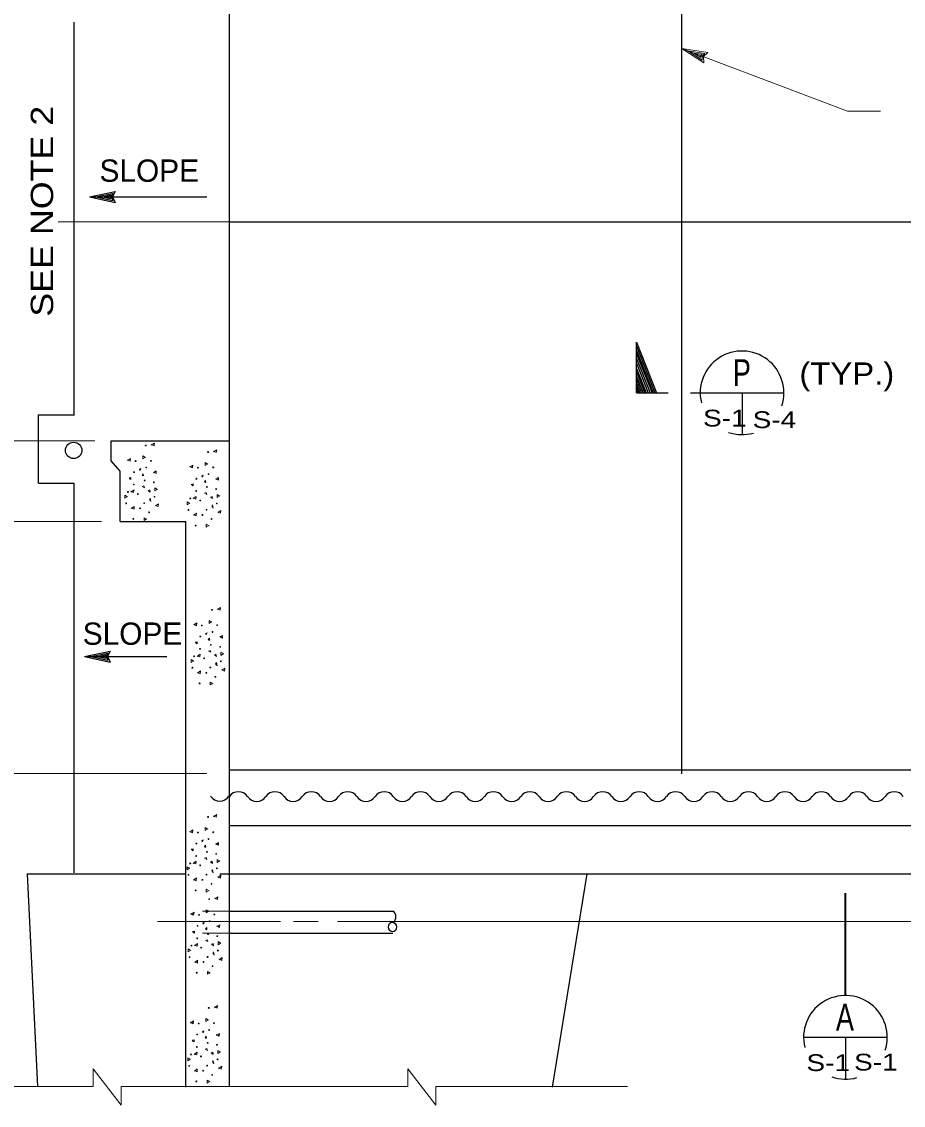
# Model space of a CAD drawing. Extents: x -24.3 to 17.7, y -17.6 to 12.4.
# Drawn here: x -19.54 to -14.6, y -0.2 to 5.87 of the extents above; entities that cross this region are included whole.
import ezdxf
from ezdxf.enums import TextEntityAlignment as Align

# ---------------------------------------------------------------- set-up
doc = ezdxf.new("R2010")
doc.units = 0
doc.header["$LTSCALE"] = 0.05
doc.linetypes.add('MEDIUM_DASHED', pattern=[4.5, 3, -1.5])
doc.layers.add('1', color=7, linetype='Continuous', lineweight=13)
doc.layers.add('2', color=7, linetype='Continuous', lineweight=13)

msp = doc.modelspace()

# ---------------------------------------------------------------- linework, layer by layer
at = {"layer": '1', "lineweight": 25}
for p, q in [((-18.37569, -0.0986), (-18.37569, 9.5474)), ((-15.84269, 1.6534), (-15.84269, 7.8164)), ((-19.24569, 3.6614), (-19.24569, 5.8654)), ((-19.15969, 4.8854), (-19.01569, 4.9164)), ((-19.15969, 4.8854), (-18.50169, 4.8854)), ((-19.15969, 4.8854), (-19.01569, 4.8544)), ((-19.12269, 4.8854), (-19.02869, 4.9054)), ((-19.12269, 4.8854), (-19.02869, 4.8654)), ((-19.08669, 4.8854), (-19.04169, 4.8954)), ((-19.08669, 4.8854), (-19.04169, 4.8764)), ((-19.04169, 4.8954), (-19.04569, 4.8854)), ((-19.04569, 4.8854), (-19.04169, 4.8764)), ((-19.02869, 4.9054), (-19.03769, 4.8854)), ((-19.03769, 4.8854), (-19.02869, 4.8654)), ((-18.37569, 4.7464), (-10.12369, 4.7464)), ((-19.44469, 3.2814), (-19.44469, 3.6644)), ((-19.44469, 3.6644), (-19.24569, 3.6644)), ((-19.03769, 3.4064), (-19.03769, 3.5184)), ((-19.03769, 3.5184), (-18.37969, 3.5184)), ((-18.98669, 3.3494), (-19.03769, 3.4064)), ((-18.98669, 3.0674), (-18.98669, 3.3494)), ((-19.44469, 3.2814), (-19.24569, 3.2814)), ((-19.24569, 1.0994), (-19.24569, 3.2814)), ((-18.98669, 3.0674), (-18.61869, 3.0674)), ((-18.61869, -0.1016), (-18.61869, 3.0674)), ((-19.18769, 2.3104), (-19.04369, 2.3414)), ((-19.18769, 2.3104), (-18.72669, 2.3104)), ((-19.18769, 2.3104), (-19.04369, 2.2794)), ((-19.15069, 2.3104), (-19.05669, 2.3304)), ((-19.15069, 2.3104), (-19.05669, 2.2904)), ((-19.11469, 2.3104), (-19.06969, 2.3204)), ((-19.11469, 2.3104), (-19.06969, 2.3014)), ((-19.06969, 2.3204), (-19.07369, 2.3104)), ((-19.07369, 2.3104), (-19.06969, 2.3014)), ((-19.05669, 2.3304), (-19.06569, 2.3104)), ((-19.06569, 2.3104), (-19.05669, 2.2904)), ((-18.37569, 1.6764), (-10.43869, 1.6764)), ((-18.37569, 1.3644), (-10.47069, 1.3644)), ((-19.50869, 1.0934), (-18.61869, 1.0934)), ((-19.50869, 1.0934), (-19.45069, -0.0986)), ((-18.42869, 1.0934), (-10.49869, 1.0934)), ((-16.37469, 1.0934), (-16.56869, -0.1026)), ((-18.37569, 0.8844), (-17.45969, 0.8844)), ((-18.37569, 0.7614), (-17.46069, 0.7614))]:
    msp.add_line(p, q, dxfattribs=at)
at = {"layer": '1'}
for p, q in [((-14.91369, 5.3654), (-15.84269, 5.7174)), ((-15.84269, 5.7174), (-15.69669, 5.6954)), ((-15.84269, 5.7174), (-15.71869, 5.6374)), ((-15.80769, 5.7044), (-15.71269, 5.6894)), ((-15.80769, 5.7044), (-15.72769, 5.6524)), ((-15.77469, 5.6914), (-15.73569, 5.6674)), ((-15.77469, 5.6914), (-15.72869, 5.6854)), ((-15.72869, 5.6854), (-15.73569, 5.6774)), ((-15.73569, 5.6774), (-15.73569, 5.6674)), ((-15.71269, 5.6894), (-15.72869, 5.6744)), ((-15.72869, 5.6744), (-15.72769, 5.6524)), ((-14.91369, 5.3654), (-14.72969, 5.3654)), ((-18.37569, 4.7464), (-19.33469, 4.7464)), ((-19.12869, 3.5184), (-20.37669, 3.5184)), ((-19.09169, 3.0674), (-20.33369, 3.0674)), ((-18.50269, 1.6554), (-21.16869, 1.6554)), ((-18.77869, 0.8254), (-18.08969, 0.8254)), ((-18.01569, 0.8254), (-17.87869, 0.8254)), ((-17.76969, 0.8254), (-13.92869, 0.8254)), ((-19.13869, -0.0986), (-19.13869, 0.0014)), ((-18.98069, -0.2036), (-19.13869, 0.0014)), ((-17.37669, -0.0986), (-17.37669, 0.0014)), ((-17.21869, -0.2036), (-17.37669, 0.0014)), ((-19.69369, -0.0986), (-19.13869, -0.0986)), ((-18.98069, -0.2036), (-18.98069, -0.0986)), ((-18.98069, -0.0986), (-17.37669, -0.0986)), ((-17.21869, -0.2036), (-17.21869, -0.0986)), ((-17.21869, -0.0986), (-16.14669, -0.0986))]:
    msp.add_line(p, q, dxfattribs=at)
at = {"layer": '1', "lineweight": 35}
msp.add_line((-14.92469, 0.4114), (-14.92469, 0.9844), dxfattribs=at)
at = {"layer": '1', "linetype": 'MEDIUM_DASHED'}
for p, q in [((-18.37569, 0.8844), (-18.61869, 0.8844)), ((-18.37569, 0.7614), (-18.61869, 0.7614))]:
    msp.add_line(p, q, dxfattribs=at)
at = {"layer": '1'}
msp.add_lwpolyline([(-15.69669, 5.6954), (-15.72069, 5.6714), (-15.71869, 5.6374)], dxfattribs=at)
at = {"layer": '1', "lineweight": 25}
for points in [[(-19.01569, 4.9164), (-19.02969, 4.8854), (-19.01569, 4.8544)], [(-19.04369, 2.3414), (-19.05769, 2.3104), (-19.04369, 2.2794)]]:
    msp.add_lwpolyline(points, dxfattribs=at)
msp.add_circle((-19.24769, 3.4654), 0.04597, dxfattribs=at)
for centre, radius, start, end in [((-18.42969, 1.5629), 0.06157, 214.0772, 325.92281), ((-18.32469, 1.4919), 0.06157, 34.0772, 145.92281), ((-18.22269, 1.5609), 0.06157, 214.0772, 325.92281), ((-18.12069, 1.4919), 0.06157, 34.0772, 145.92281), ((-18.01869, 1.5609), 0.06157, 214.0772, 325.92281), ((-17.91669, 1.4919), 0.06157, 34.0772, 145.92281), ((-17.81469, 1.5609), 0.06157, 214.0772, 325.92281), ((-17.71269, 1.4919), 0.06157, 34.0772, 145.92281), ((-17.61069, 1.5609), 0.06157, 214.0772, 325.92281), ((-17.50869, 1.4919), 0.06157, 34.0772, 145.92281), ((-17.40669, 1.5609), 0.06157, 214.0772, 325.92281), ((-17.30469, 1.4919), 0.06157, 34.0772, 145.92281), ((-17.20269, 1.5609), 0.06157, 214.0772, 325.92281), ((-17.10069, 1.4919), 0.06157, 34.0772, 145.92281), ((-16.99869, 1.5609), 0.06157, 214.0772, 325.92281), ((-16.89669, 1.4919), 0.06157, 34.0772, 145.92281), ((-16.79469, 1.5609), 0.06157, 214.0772, 325.92281), ((-16.69269, 1.4919), 0.06157, 34.0772, 145.92281), ((-16.59069, 1.5609), 0.06157, 214.0772, 325.92281), ((-16.48869, 1.4919), 0.06157, 34.0772, 145.92281), ((-16.38669, 1.5609), 0.06157, 214.0772, 325.92281), ((-16.28469, 1.4919), 0.06157, 34.0772, 145.92281), ((-16.18269, 1.5609), 0.06157, 214.0772, 325.92281), ((-16.08069, 1.4919), 0.06157, 34.0772, 145.92281), ((-15.97869, 1.5609), 0.06157, 214.0772, 325.92281), ((-15.87669, 1.4919), 0.06157, 34.0772, 145.92281), ((-15.77469, 1.5609), 0.06157, 214.0772, 325.92281), ((-15.67269, 1.4919), 0.06157, 34.0772, 145.92281), ((-15.57069, 1.5609), 0.06157, 214.0772, 325.92281), ((-15.46869, 1.4919), 0.06157, 34.0772, 145.92281), ((-15.36669, 1.5609), 0.06157, 214.0772, 325.92281), ((-15.26469, 1.4919), 0.06157, 34.0772, 145.92281), ((-15.16269, 1.5609), 0.06157, 214.0772, 325.92281), ((-15.06069, 1.4919), 0.06157, 34.0772, 145.92281), ((-14.95869, 1.5609), 0.06157, 214.0772, 325.92281), ((-14.85669, 1.4919), 0.06157, 34.0772, 145.92281), ((-14.75469, 1.5609), 0.06157, 214.0772, 325.92281), ((-14.65269, 1.4919), 0.06157, 34.0772, 145.92281), ((-17.48075, 0.85268), 0.03807, 307.28682, 56.4084)]:
    msp.add_arc(centre, radius, start, end, dxfattribs=at)
msp.add_ellipse((-17.46219, 0.7954), major_axis=(-0.0005, 0.027), ratio=0.833928, dxfattribs=at)
at = {"layer": '2', "lineweight": 25}
for p, q in [((-16.09569, 4.0494), (-15.99269, 3.7884)), ((-16.09569, 4.0244), (-16.00169, 3.7884)), ((-16.09569, 4.0074), (-16.00869, 3.7884)), ((-16.09569, 3.9804), (-16.01969, 3.7884)), ((-16.09569, 3.9544), (-16.02969, 3.7884)), ((-16.09569, 3.9244), (-16.04169, 3.7884)), ((-16.09569, 3.9034), (-16.04969, 3.7884)), ((-16.09569, 3.8794), (-16.05869, 3.7884)), ((-16.09569, 3.8584), (-16.06769, 3.7884)), ((-16.09569, 3.8364), (-16.07669, 3.7884)), ((-16.09569, 3.8214), (-16.08269, 3.7884)), ((-16.09569, 3.8014), (-16.09069, 3.7884)), ((-16.09569, 3.7884), (-15.91869, 3.7884)), ((-15.79369, 3.7884), (-15.73869, 3.7884)), ((-15.73869, 3.7884), (-15.27069, 3.7884)), ((-15.50469, 3.7884), (-15.50469, 3.5544)), ((-15.15969, 0.1774), (-14.69169, 0.1774)), ((-14.92569, 0.1774), (-14.92569, -0.0566))]:
    msp.add_line(p, q, dxfattribs=at)
at = {"layer": '2'}
for p, q in [((-18.92869, 3.3034), (-18.93669, 3.3124)), ((-18.57969, 3.2664), (-18.58769, 3.2754)), ((-18.55769, 2.3824), (-18.56569, 2.3914)), ((-18.57969, 1.2224), (-18.58769, 1.2314)), ((-18.57369, 0.7614), (-18.58169, 0.7704)), ((-18.57569, 0.1524), (-18.58369, 0.1614))]:
    msp.add_line(p, q, dxfattribs=at)
at = {"layer": '2', "lineweight": 25}
msp.add_lwpolyline([(-16.09569, 3.7884), (-16.09569, 4.0724), (-15.98369, 3.7884)], dxfattribs=at)
at = {"layer": '2'}
for points in [[(-18.81269, 3.4984), (-18.79769, 3.4914), (-18.79569, 3.5064), (-18.81269, 3.4944)], [(-18.46369, 3.4614), (-18.44869, 3.4544), (-18.44669, 3.4694), (-18.46369, 3.4574)], [(-18.94569, 3.4124), (-18.93069, 3.4044), (-18.92869, 3.4204), (-18.94569, 3.4084)], [(-18.84769, 3.4254), (-18.86069, 3.4174), (-18.86069, 3.4344), (-18.84469, 3.4254)], [(-18.87669, 3.3534), (-18.87969, 3.3604), (-18.87169, 3.3644), (-18.87569, 3.3534)], [(-18.80069, 3.3434), (-18.78569, 3.3354), (-18.78469, 3.3504), (-18.80069, 3.3394)], [(-18.59669, 3.3754), (-18.58169, 3.3674), (-18.57969, 3.3834), (-18.59669, 3.3714)], [(-18.49869, 3.3884), (-18.51169, 3.3804), (-18.51169, 3.3974), (-18.49569, 3.3884)], [(-18.93769, 3.3124), (-18.92669, 3.3144), (-18.92669, 3.3034)], [(-18.85769, 3.3224), (-18.86469, 3.3274), (-18.85769, 3.3344), (-18.85669, 3.3234)], [(-18.52769, 3.3164), (-18.53069, 3.3234), (-18.52269, 3.3274), (-18.52669, 3.3164)], [(-18.50869, 3.2854), (-18.51569, 3.2904), (-18.50869, 3.2974), (-18.50769, 3.2864)], [(-18.45169, 3.3064), (-18.43669, 3.2984), (-18.43569, 3.3134), (-18.45169, 3.3024)], [(-18.92669, 3.2364), (-18.91169, 3.2294), (-18.90969, 3.2444), (-18.92669, 3.2324)], [(-18.78069, 3.2464), (-18.79369, 3.2384), (-18.79369, 3.2554), (-18.77769, 3.2464)], [(-18.58869, 3.2754), (-18.57769, 3.2774), (-18.57769, 3.2664)], [(-18.43169, 3.2094), (-18.44469, 3.2014), (-18.44469, 3.2184), (-18.42869, 3.2094)], [(-18.94769, 3.2054), (-18.96069, 3.1974), (-18.96069, 3.2144), (-18.94569, 3.2054)], [(-18.81869, 3.1834), (-18.82369, 3.1904), (-18.81869, 3.1974), (-18.81569, 3.1794)], [(-18.78869, 3.1574), (-18.77369, 3.1504), (-18.77169, 3.1664), (-18.78869, 3.1544)], [(-18.59869, 3.1684), (-18.61169, 3.1604), (-18.61169, 3.1774), (-18.59669, 3.1684)], [(-18.57769, 3.1994), (-18.56269, 3.1924), (-18.56069, 3.2074), (-18.57769, 3.1954)], [(-18.46969, 3.1464), (-18.47469, 3.1534), (-18.46969, 3.1604), (-18.46669, 3.1424)], [(-18.92469, 3.1424), (-18.90969, 3.1354), (-18.90869, 3.1514), (-18.92469, 3.1394)], [(-18.57569, 3.1054), (-18.56069, 3.0984), (-18.55969, 3.1144), (-18.57569, 3.1024)], [(-18.43969, 3.1204), (-18.42469, 3.1134), (-18.42269, 3.1294), (-18.43969, 3.1174)], [(-18.84069, 3.0794), (-18.85369, 3.0724), (-18.85369, 3.0884), (-18.83869, 3.0794)], [(-18.49169, 3.0424), (-18.50469, 3.0354), (-18.50469, 3.0514), (-18.48969, 3.0424)], [(-18.44169, 2.5774), (-18.42669, 2.5704), (-18.42469, 2.5854), (-18.44169, 2.5734)], [(-18.57469, 2.4914), (-18.55969, 2.4834), (-18.55769, 2.4994), (-18.57469, 2.4874)], [(-18.47669, 2.5044), (-18.48969, 2.4964), (-18.48969, 2.5134), (-18.47369, 2.5044)], [(-18.50569, 2.4324), (-18.50869, 2.4394), (-18.50069, 2.4434), (-18.50469, 2.4324)], [(-18.42969, 2.4224), (-18.41469, 2.4144), (-18.41369, 2.4294), (-18.42969, 2.4184)], [(-18.56669, 2.3914), (-18.55569, 2.3934), (-18.55569, 2.3824)], [(-18.48669, 2.4014), (-18.49369, 2.4064), (-18.48669, 2.4134), (-18.48569, 2.4024)], [(-18.55569, 2.3154), (-18.54069, 2.3084), (-18.53869, 2.3234), (-18.55569, 2.3114)], [(-18.40969, 2.3254), (-18.42269, 2.3174), (-18.42269, 2.3344), (-18.40669, 2.3254)], [(-18.57669, 2.2844), (-18.58969, 2.2764), (-18.58969, 2.2934), (-18.57469, 2.2844)], [(-18.44769, 2.2624), (-18.45269, 2.2694), (-18.44769, 2.2764), (-18.44469, 2.2584)], [(-18.55369, 2.2214), (-18.53869, 2.2144), (-18.53769, 2.2304), (-18.55369, 2.2184)], [(-18.41769, 2.2364), (-18.40269, 2.2294), (-18.40069, 2.2454), (-18.41769, 2.2334)], [(-18.46969, 2.1584), (-18.48269, 2.1514), (-18.48269, 2.1674), (-18.46769, 2.1584)], [(-18.46369, 1.4174), (-18.44869, 1.4104), (-18.44669, 1.4254), (-18.46369, 1.4134)], [(-18.59669, 1.3314), (-18.58169, 1.3234), (-18.57969, 1.3394), (-18.59669, 1.3274)], [(-18.49869, 1.3444), (-18.51169, 1.3364), (-18.51169, 1.3534), (-18.49569, 1.3444)], [(-18.52769, 1.2724), (-18.53069, 1.2794), (-18.52269, 1.2834), (-18.52669, 1.2724)], [(-18.58869, 1.2314), (-18.57769, 1.2334), (-18.57769, 1.2224)], [(-18.50869, 1.2414), (-18.51569, 1.2464), (-18.50869, 1.2534), (-18.50769, 1.2424)], [(-18.45169, 1.2624), (-18.43669, 1.2544), (-18.43569, 1.2694), (-18.45169, 1.2584)], [(-18.57769, 1.1554), (-18.56269, 1.1484), (-18.56069, 1.1634), (-18.57769, 1.1514)], [(-18.43169, 1.1654), (-18.44469, 1.1574), (-18.44469, 1.1744), (-18.42869, 1.1654)], [(-18.59869, 1.1244), (-18.61169, 1.1164), (-18.61169, 1.1334), (-18.59669, 1.1244)], [(-18.46969, 1.1024), (-18.47469, 1.1094), (-18.46969, 1.1164), (-18.46669, 1.0984)], [(-18.57569, 1.0614), (-18.56069, 1.0544), (-18.55969, 1.0704), (-18.57569, 1.0584)], [(-18.43969, 1.0764), (-18.42469, 1.0694), (-18.42269, 1.0854), (-18.43969, 1.0734)], [(-18.49169, 0.9984), (-18.50469, 0.9914), (-18.50469, 1.0074), (-18.48969, 0.9984)], [(-18.45769, 0.9564), (-18.44269, 0.9494), (-18.44069, 0.9644), (-18.45769, 0.9524)], [(-18.59069, 0.8704), (-18.57569, 0.8624), (-18.57369, 0.8784), (-18.59069, 0.8664)], [(-18.49269, 0.8834), (-18.50569, 0.8754), (-18.50569, 0.8924), (-18.48969, 0.8834)], [(-18.52169, 0.8114), (-18.52469, 0.8184), (-18.51669, 0.8224), (-18.52069, 0.8114)], [(-18.50269, 0.7804), (-18.50969, 0.7854), (-18.50269, 0.7924), (-18.50169, 0.7814)], [(-18.44569, 0.8014), (-18.43069, 0.7934), (-18.42969, 0.8084), (-18.44569, 0.7974)], [(-18.58269, 0.7704), (-18.57169, 0.7724), (-18.57169, 0.7614)], [(-18.59269, 0.6634), (-18.60569, 0.6554), (-18.60569, 0.6724), (-18.59069, 0.6634)], [(-18.57169, 0.6944), (-18.55669, 0.6874), (-18.55469, 0.7024), (-18.57169, 0.6904)], [(-18.42569, 0.7044), (-18.43869, 0.6964), (-18.43869, 0.7134), (-18.42269, 0.7044)], [(-18.56969, 0.6004), (-18.55469, 0.5934), (-18.55369, 0.6094), (-18.56969, 0.5974)], [(-18.46369, 0.6414), (-18.46869, 0.6484), (-18.46369, 0.6554), (-18.46069, 0.6374)], [(-18.43369, 0.6154), (-18.41869, 0.6084), (-18.41669, 0.6244), (-18.43369, 0.6124)], [(-18.48569, 0.5374), (-18.49869, 0.5304), (-18.49869, 0.5464), (-18.48369, 0.5374)], [(-18.45969, 0.3474), (-18.44469, 0.3404), (-18.44269, 0.3554), (-18.45969, 0.3434)], [(-18.59269, 0.2614), (-18.57769, 0.2534), (-18.57569, 0.2694), (-18.59269, 0.2574)], [(-18.49469, 0.2744), (-18.50769, 0.2664), (-18.50769, 0.2834), (-18.49169, 0.2744)], [(-18.52369, 0.2024), (-18.52669, 0.2094), (-18.51869, 0.2134), (-18.52269, 0.2024)], [(-18.50469, 0.1714), (-18.51169, 0.1764), (-18.50469, 0.1834), (-18.50369, 0.1724)], [(-18.44769, 0.1924), (-18.43269, 0.1844), (-18.43169, 0.1994), (-18.44769, 0.1884)], [(-18.58469, 0.1614), (-18.57369, 0.1634), (-18.57369, 0.1524)], [(-18.59469, 0.0544), (-18.60769, 0.0464), (-18.60769, 0.0634), (-18.59269, 0.0544)], [(-18.57369, 0.0854), (-18.55869, 0.0784), (-18.55669, 0.0934), (-18.57369, 0.0814)], [(-18.42769, 0.0954), (-18.44069, 0.0874), (-18.44069, 0.1044), (-18.42469, 0.0954)], [(-18.57169, -0.0086), (-18.55669, -0.0156), (-18.55569, 0.0004), (-18.57169, -0.0116)], [(-18.46569, 0.0324), (-18.47069, 0.0394), (-18.46569, 0.0464), (-18.46269, 0.0284)], [(-18.43569, 0.0064), (-18.42069, -0.0006), (-18.41869, 0.0154), (-18.43569, 0.0034)], [(-18.48769, -0.0716), (-18.50069, -0.0786), (-18.50069, -0.0626), (-18.48569, -0.0716)]]:
    msp.add_lwpolyline(points, dxfattribs=at)
for points in [[(-18.85069, 3.2554), (-18.86369, 3.2624), (-18.85469, 3.2664)], [(-18.81869, 3.2324), (-18.83069, 3.2404), (-18.82169, 3.2444)], [(-18.50169, 3.2184), (-18.51469, 3.2254), (-18.50569, 3.2294)], [(-18.46969, 3.1954), (-18.48169, 3.2034), (-18.47269, 3.2074)], [(-18.47969, 2.3344), (-18.49269, 2.3414), (-18.48369, 2.3454)], [(-18.44769, 2.3114), (-18.45969, 2.3194), (-18.45069, 2.3234)], [(-18.50169, 1.1744), (-18.51469, 1.1814), (-18.50569, 1.1854)], [(-18.46969, 1.1514), (-18.48169, 1.1594), (-18.47269, 1.1634)], [(-18.49569, 0.7134), (-18.50869, 0.7204), (-18.49969, 0.7244)], [(-18.46369, 0.6904), (-18.47569, 0.6984), (-18.46669, 0.7024)], [(-18.49769, 0.1044), (-18.51069, 0.1114), (-18.50169, 0.1154)], [(-18.46569, 0.0814), (-18.47769, 0.0894), (-18.46869, 0.0934)]]:
    msp.add_lwpolyline(points, close=True, dxfattribs=at)
for centre in [(-18.84412, 3.49315), (-18.90075, 3.40577), (-18.81488, 3.40727), (-18.49512, 3.45615), (-18.90938, 3.3439), (-18.8415, 3.3694), (-18.55175, 3.36877), (-18.46588, 3.37027), (-18.85012, 3.2974), (-18.79838, 3.28615), (-18.56038, 3.3069), (-18.4925, 3.3324), (-18.9435, 3.2329), (-18.91088, 3.27452), (-18.888, 3.22165), (-18.56188, 3.23752), (-18.50112, 3.2604), (-18.44937, 3.24915), (-18.95362, 3.16877), (-18.85275, 3.1699), (-18.79462, 3.20515), (-18.5945, 3.1959), (-18.539, 3.18465), (-18.44562, 3.16815), (-18.87562, 3.14102), (-18.825, 3.11815), (-18.60462, 3.13177), (-18.52662, 3.10402), (-18.50375, 3.1329), (-18.9135, 3.0814), (-18.5645, 3.0444), (-18.476, 3.08115), (-18.47312, 2.57215), (-18.52975, 2.48477), (-18.4705, 2.4484), (-18.44387, 2.48627), (-18.53837, 2.4229), (-18.47912, 2.3764), (-18.5725, 2.3119), (-18.53987, 2.35352), (-18.42737, 2.36515), (-18.58263, 2.24777), (-18.517, 2.30065), (-18.48175, 2.2489), (-18.42362, 2.28415), (-18.50463, 2.22002), (-18.454, 2.19715), (-18.5425, 2.1604), (-18.49512, 1.41215), (-18.55175, 1.32477), (-18.4925, 1.2884), (-18.46588, 1.32627), (-18.56038, 1.2629), (-18.50112, 1.2164), (-18.5945, 1.1519), (-18.56188, 1.19352), (-18.44937, 1.20515), (-18.539, 1.14065), (-18.44562, 1.12415), (-18.60462, 1.08777), (-18.52662, 1.06002), (-18.50375, 1.0889), (-18.476, 1.03715), (-18.5645, 1.0004), (-18.48912, 0.95115), (-18.54575, 0.86377), (-18.45988, 0.86527), (-18.55438, 0.8019), (-18.4865, 0.8274), (-18.55588, 0.73252), (-18.49512, 0.7554), (-18.44337, 0.74415), (-18.5885, 0.6909), (-18.533, 0.67965), (-18.59862, 0.62677), (-18.49775, 0.6279), (-18.43962, 0.66315), (-18.52062, 0.59902), (-18.47, 0.57615), (-18.5585, 0.5394), (-18.49113, 0.34215), (-18.54775, 0.25477), (-18.46187, 0.25627), (-18.55637, 0.1929), (-18.4885, 0.2184), (-18.55787, 0.12352), (-18.49713, 0.1464), (-18.44537, 0.13515), (-18.5905, 0.0819), (-18.535, 0.07065), (-18.60063, 0.01777), (-18.49975, 0.0189), (-18.44162, 0.05415), (-18.52262, -0.00998), (-18.472, -0.03285), (-18.5605, -0.0696)]:
    msp.add_circle(centre, 0.00244, dxfattribs=at)
at = {"layer": '2', "lineweight": 25}
for centre, start, end in [((-15.50494, 3.78815), 341.96976, 193.81208), ((-15.50494, 3.78815), 251.04049, 285.74671), ((-14.92594, 0.17715), 341.96976, 193.81208), ((-14.92594, 0.17715), 251.04049, 285.74671)]:
    msp.add_arc(centre, 0.23438, start, end, dxfattribs=at)

# ---------------------------------------------------------------- texts
at = {"layer": '1', "width": 1.2}
msp.add_text('SEE NOTE 2', height=0.125, rotation=90, dxfattribs=at).set_placement((-19.36269, 4.8054), align=Align.CENTER)
at = {"layer": '1'}
for p in [(-18.82419, 4.9704), (-18.91819, 2.3764)]:
    msp.add_text('SLOPE', height=0.125, dxfattribs=at).set_placement(p, align=Align.CENTER)
at = {"layer": '1', "width": 1.1}
msp.add_text('(TYP.)', height=0.125, dxfattribs=at).set_placement((-15.18369, 3.8334))
at = {"layer": '2'}
for s, height, width, p in [('P', 0.15, 0.75, (-15.50569, 3.8264)), ('S-1', 0.094, 1.25, (-15.60119, 3.5994)), ('S-4', 0.094, 1.25, (-15.32319, 3.5904)), ('A', 0.15, 0.75, (-14.92869, 0.2154)), ('S-1', 0.094, 1.25, (-15.02219, -0.0116)), ('S-1', 0.094, 1.25, (-14.75519, -0.0086))]:
    msp.add_text(s, height=height, dxfattribs=dict(at, width=width)).set_placement(p, align=Align.CENTER)

doc.saveas('drawing.dxf')
